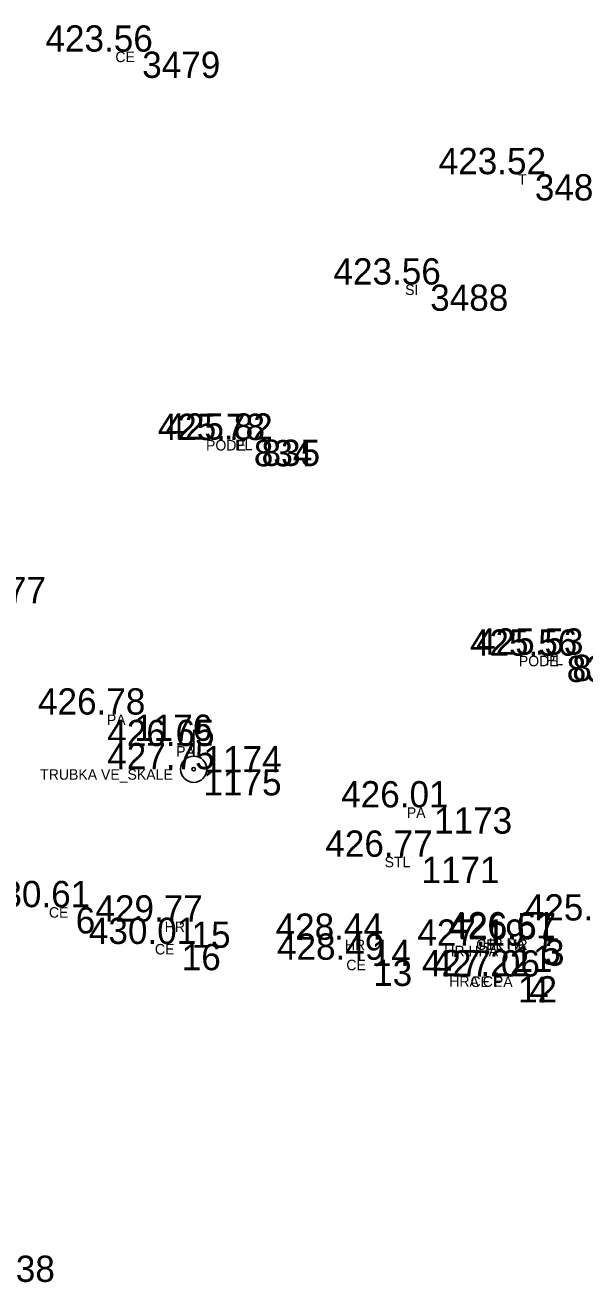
# Model space of a CAD drawing. Extents: x -639390 to -639075, y -1138747 to -1138358.
# Drawn here: x -639174.81 to -639158.84, y -1138659.59 to -1138623.93 of the extents above; entities that cross this region are included whole.
import ezdxf

# ---------------------------------------------------------------- set-up
doc = ezdxf.new("R2010")
doc.units = 0
for name, color, linetype in [('Vrstva 11', 7, 'Continuous'), ('Vrstva 12', 7, 'Continuous'), ('Vrstva 13', 7, 'Continuous'), ('Vrstva 21', 7, 'Continuous'), ('Vrstva 57', 7, 'Continuous')]:
    doc.layers.add(name, color=color, linetype=linetype)

msp = doc.modelspace()

# ---------------------------------------------------------------- linework, layer by layer
at = {"layer": 'Vrstva 11'}
for p, q in [((-639171.74, -1138624.69), (-639171.74, -1138624.69)), ((-639160.52, -1138628.19), (-639160.52, -1138628.19)), ((-639163.51, -1138631.34), (-639163.51, -1138631.34)), ((-639168.55, -1138635.78), (-639168.55, -1138635.78)), ((-639168.33, -1138635.77), (-639168.33, -1138635.77)), ((-639159.61, -1138641.94), (-639159.61, -1138641.94)), ((-639159.45, -1138641.91), (-639159.45, -1138641.91)), ((-639171.97, -1138643.62), (-639171.97, -1138643.62)), ((-639169.99, -1138644.52), (-639169.99, -1138644.52)), ((-639169.99, -1138645.18), (-639169.99, -1138645.18)), ((-639163.4, -1138646.27), (-639163.4, -1138646.27)), ((-639163.76, -1138647.68), (-639163.76, -1138647.68)), ((-639173.64, -1138649.12), (-639173.64, -1138649.12)), ((-639170.33, -1138649.53), (-639170.33, -1138649.53)), ((-639170.61, -1138650.17), (-639170.61, -1138650.17)), ((-639165.18, -1138650.05), (-639165.18, -1138650.05)), ((-639161.13, -1138650.22), (-639161.13, -1138650.22)), ((-639160.34, -1138650.01), (-639160.34, -1138650.01)), ((-639160.23, -1138650.04), (-639160.23, -1138650.04)), ((-639165.14, -1138650.62), (-639165.14, -1138650.62)), ((-639161, -1138651.09), (-639161, -1138651.09)), ((-639160.68, -1138651.1), (-639160.68, -1138651.1))]:
    msp.add_line(p, q, dxfattribs=at)
at = {"layer": 'Vrstva 21'}
msp.add_line((-639169.99, -1138644.805), (-639169.99, -1138644.055), dxfattribs=at)
for radius in [0.375, 0.05]:
    msp.add_circle((-639169.99, -1138645.18), radius, dxfattribs=at)

# ---------------------------------------------------------------- texts
at = {"layer": 'Vrstva 12'}
for s, p in [('423.56 ', (-639174.226, -1138624.69)), ('423.52 ', (-639162.989, -1138628.19)), ('423.56 ', (-639165.996, -1138631.34)), ('425.78 ', (-639171.019, -1138635.78)), ('425.82 ', (-639170.799, -1138635.77)), ('425.56 ', (-639162.096, -1138641.94)), ('425.53 ', (-639161.919, -1138641.91)), ('426.78 ', (-639174.439, -1138643.62)), ('426.65 ', (-639172.46, -1138644.52)), ('427.75 ', (-639172.46, -1138645.18)), ('426.01 ', (-639165.775, -1138646.27)), ('426.77 ', (-639166.229, -1138647.68)), ('430.61 ', (-639176.015, -1138649.12)), ('429.77 ', (-639172.799, -1138649.53)), ('425.83 ', (-639160.529, -1138649.5)), ('430.01 ', (-639172.985, -1138650.17)), ('428.44 ', (-639167.649, -1138650.05)), ('427.19 ', (-639163.599, -1138650.22)), ('426.61 ', (-639162.715, -1138650.01)), ('426.57 ', (-639162.699, -1138650.04)), ('428.49 ', (-639167.609, -1138650.62)), ('427.22 ', (-639163.469, -1138651.09)), ('427.06 ', (-639163.166, -1138651.1))]:
    msp.add_text(s, height=0.75, dxfattribs=at).set_placement(p)
at = {"layer": 'Vrstva 13'}
for s, p in [(' 3479', (-639171.74, -1138625.44)), (' 3487', (-639160.52, -1138628.94)), (' 3488', (-639163.51, -1138632.09)), (' 834', (-639168.55, -1138636.53)), (' 835', (-639168.33, -1138636.52)), (' 1177', (-639176.72, -1138640.44)), (' 837', (-639159.61, -1138642.69)), (' 836', (-639159.45, -1138642.66)), (' 1176', (-639171.97, -1138644.37)), (' 1174', (-639169.99, -1138645.27)), (' 1175', (-639169.99, -1138645.93)), (' 1173', (-639163.4, -1138647.02)), (' 1171', (-639163.76, -1138648.43)), (' 6', (-639173.64, -1138649.87)), (' 15', (-639170.33, -1138650.28)), (' 16', (-639170.61, -1138650.92)), (' 14', (-639165.18, -1138650.8)), (' 11', (-639161.13, -1138650.97)), (' 5', (-639160.34, -1138650.76)), (' 3', (-639160.23, -1138650.79)), (' 13', (-639165.14, -1138651.37)), (' 12', (-639161, -1138651.84)), (' 4', (-639160.68, -1138651.85)), (' 538', (-639175.91, -1138659.82))]:
    msp.add_text(s, height=0.75, dxfattribs=at).set_placement(p)
at = {"layer": 'Vrstva 57'}
for s, p in [('CE', (-639172.228, -1138624.99)), ('T', (-639160.72, -1138628.49)), ('SI', (-639163.948, -1138631.64)), ('PODE', (-639169.638, -1138636.08)), ('PL', (-639168.805, -1138636.07)), ('PODE', (-639160.698, -1138642.24)), ('PL', (-639159.925, -1138642.21)), ('PA', (-639172.47, -1138643.92)), ('PA', (-639170.49, -1138644.82)), ('TRUBKA VE_SKALE', (-639174.378, -1138645.48)), ('PA', (-639163.9, -1138646.57)), ('STL', (-639164.535, -1138647.98)), ('CE', (-639174.128, -1138649.42)), ('HR', (-639170.819, -1138649.83)), ('CE', (-639171.098, -1138650.47)), ('HR', (-639165.669, -1138650.35)), ('HR HRA', (-639162.83, -1138650.52)), ('CEL HR', (-639161.919, -1138650.34)), ('HR PA', (-639161.74, -1138650.31)), ('CE', (-639165.628, -1138650.92)), ('HRA CE', (-639162.688, -1138651.39)), ('CE PA', (-639162.08, -1138651.4))]:
    msp.add_text(s, height=0.3, dxfattribs=at).set_placement(p)

doc.saveas('drawing.dxf')
